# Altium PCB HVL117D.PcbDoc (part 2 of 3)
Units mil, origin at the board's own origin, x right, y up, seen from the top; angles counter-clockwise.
Board outline 2004.03 x 2004.03 mil, 6 copper layers (Top Layer, InternalPlane1, MidLayer1, InternalPlane2, MidLayer2, Bottom Layer), stack 60.56 mil thick; 218 components, 157 nets, 658 pads, 273 vias.
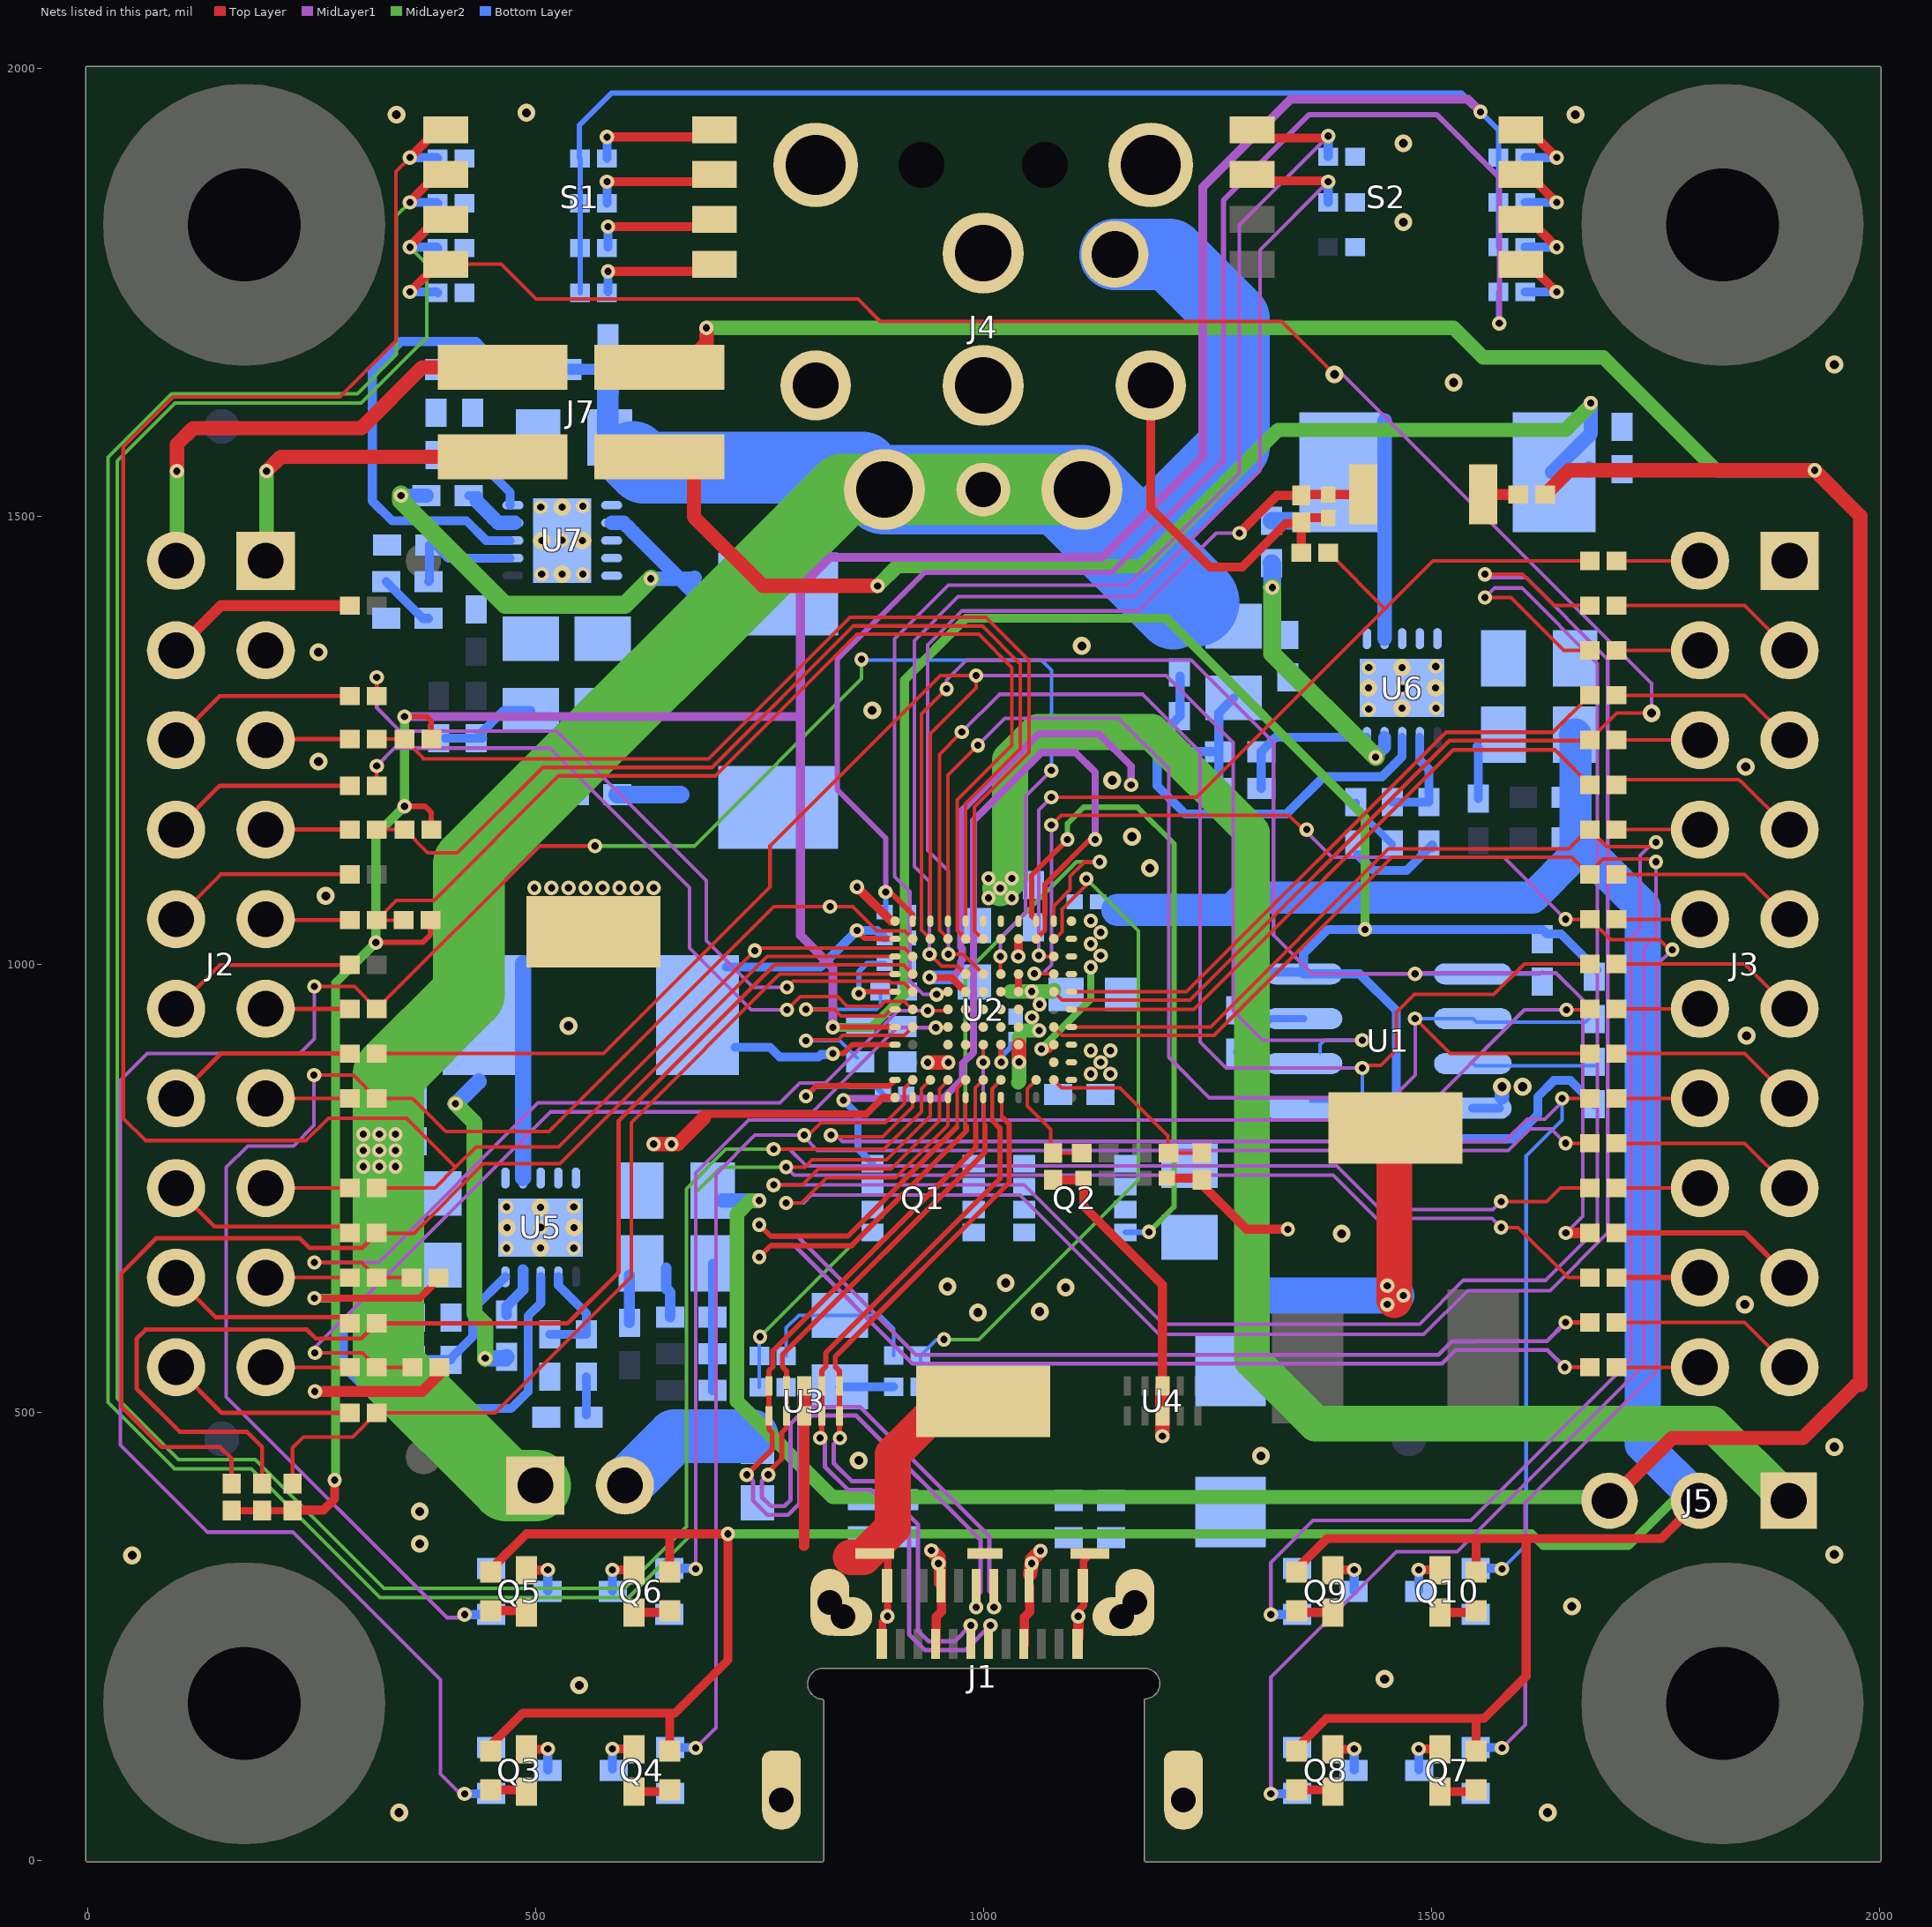
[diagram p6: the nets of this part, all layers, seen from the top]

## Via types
v1: diameter 16, hole 8, Top Layer to Bottom Layer, tented both sides, 166 vias
v2: diameter 16, hole 8.1, Top Layer to Bottom Layer, tented both sides, 54 vias
v3: diameter 20, hole 10, Top Layer to Bottom Layer, tented both sides, 41 vias
v4: diameter 19.68, hole 7.87, Top Layer to Bottom Layer, 12 vias

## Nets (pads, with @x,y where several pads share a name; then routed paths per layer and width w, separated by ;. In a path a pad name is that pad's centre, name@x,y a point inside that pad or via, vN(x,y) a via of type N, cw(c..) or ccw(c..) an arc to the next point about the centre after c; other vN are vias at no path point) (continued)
C_USB_B_N: J1.B7 U2.L7 U3.1 U3.10 | length 806.4
  Top Layer w4: 1020.68,828.32 U2.L7@1020.68,848.94
  Top Layer w5.8: v1(840,471) 839.37,471.63 U3.10@839.37,495.64 U3.1@839.37,529.1 839.37,546 834.8,550.57 834.8,561.8 1029,756 1029,821.27 1022.27,828
  MidLayer1 w4.8: v1(840,471) 833,464 833,443 853,423 878.86,423 927,374.86 927,256 939,244 968,244 v1(986,262)
C_USB_B_P: J1.B6 U2.K7 U3.2 U3.9 | length 875.1
  Top Layer w4: 1010,828 1010,860.94 U2.K7@1019.68,870.63
  Top Layer w5.8: v1(818,471) 819.69,472.69 U3.9@819.69,495.64 U3.2@819.69,529.1 819.69,546 824.25,550.57 824.25,566.17 1018.45,760.37 1018.45,816.9 1010,825.35 1010,828
  MidLayer1 w4.8: v1(818,471) 823.2,465.8 823.2,438.94 848.94,413.2 874.8,413.2 917.2,370.8 917.2,251.94 934.94,234.2 980.2,234.2 v1(1008,262)
C_USB_T_N: J1.A7 U2.L6 U3.4 U3.7 | length 1057.1
  Top Layer w4: 1001,820 U2.L6@1001,848.94
  Top Layer w5.8: v1@756,429 758.5,431.5 775,448 775,477 780.32,482.32 U3.7@780.32,495.64 U3.4@780.32,529.1 780.32,546 775.75,550.57 775.75,564 1002,790.25 1002,820
  MidLayer1 w4.8: v1(760,430) 752.9,422.9 752.9,405 762.9,395 778,395 785,402 785,486.86 803.94,505.8 862.2,505.8 1006.9,361.1 1006.9,300.1 1012,295 v1(1012,282) 1011,281 1011,278 1012.75,279.75 v1@1012.75,281.5
C_USB_T_P: J1.A6 U2.K6 U3.5 U3.6 | length 1076.2
  Top Layer w4: 991,822 991,861.63 U2.K6@1000,870.63
  Top Layer w5.8: v1(736,430) 764.45,458.45 764.45,477 760.63,480.82 U3.6@760.63,495.64 U3.5@760.63,529.1 760.63,546 765.2,550.57 765.2,568.37 991.45,794.62 991.45,822
  MidLayer1 w4.8: v1(736,430) 743.1,422.9 743.1,400.94 758.84,385.2 782.06,385.2 794.8,397.94 794.8,482.8 808,496 858.14,496 997.1,357.04 997.1,299.1 992,294 v1(992,282)
DEBUG_1: Q10.1 R61.1 U2.L2 | length 1570.6
  Top Layer w4: v1@829,813.37 835.37,807 887.63,807 921.26,840.63 U2.L2@921.26,850.94 ; v1@1650,850 R61.1@1677.04,850
  MidLayer1 w4: v1(830,809) 836,809 843,802 1582,802 1607,827 1627,827 v1@1650,850
  Bottom Layer w4: v1(1579,325) 1606,352 1606,786 1646,826 v1(1646,850)
  Bottom Layer w10: Q10.1@1549.5,325.59 v1@1578.41,325.59
DEBUG_2: Q4.1 R64.1 U2.K2 | length 1847.9
  Top Layer w4: v1@805,809 819,823 890.63,823 911.91,844.28 911.91,846.55 912,846.63 912,855.26 911.91,855.34 911.91,861.28 U2.K2@921.26,870.63 ; v1(1650,800) R64.1@1677.04,800
  MidLayer1 w4: v1(679,125) 701.5,147.5 701.5,765.5 745,809 v1(800,809) 800,807 815,792 1586.14,792 1610.14,816 1634,816 v1(1650,800)
  Bottom Layer w10: Q4.1@650.5,125.59 v1@678.41,125.59
DEBUG_3: R29.1 R65.1 S1.2 U2.L3 | length 4097
  Top Layer w4: v1(780,773.37) 801,773.37 809,781.37 892,781.37 940.94,830.32 U2.L3@940.94,850.94 ; v1(1578,706) 1597,706 1653,650 R65.1@1677.04,650
  Top Layer w10: v1(360,1850) 359,1850 S1.2@390,1881
  MidLayer1 w4: v1(780,773.37) 788.87,764.5 1390.5,764.5 1439,716 1568,716 v1(1578,706)
  MidLayer2 w4: v1(360,1850) 345,1835 345,1680 301.37,1636.37 93.7,1636.37 23,1565.67 23,511 97.37,436.63 183.01,436.63 326.64,293 604,293 679,368 679,745 707.37,773.37 v1(780,773.37)
  Bottom Layer w10: v1(360,1850) 390.04,1850 R29.1@391.04,1849
DEBUG_4: R25.1 R63.1 S1.3 U2.K3 | length 4045.7
  Top Layer w4: v1(766,793.37) 889,793.37 931,835.37 931,860.68 U2.K3@940.94,870.63 ; v1(1578,735) 1629,735 1644,750 R63.1@1677.04,750
  Top Layer w10: v1(360,1800) 359,1800 S1.3@388,1829
  MidLayer1 w4: v1(766,793.37) 783.63,793.37 802.5,774.5 1394.64,774.5 1443.14,726 1569,726 v1(1578,735)
  MidLayer2 w4: v1(360,1800) 379,1781 379,1699.33 305.67,1626 98,1626 33.37,1561.37 33.37,515.3 101.67,447 187.3,447 330.93,303.37 599.7,303.37 668.63,372.3 668.63,749.3 712.7,793.37 v1(766,793.37)
  Bottom Layer w10: v1(360,1800) 390.04,1800 R25.1@391.04,1799
DEBUG_CTL1: R55.1 S2.1 U2.E4 | length 1422
  Top Layer w4: v1@948,965 952.06,969.06 U2.E4@960.63,969.06
  Top Layer w10: S2.1@1306,1922 1383,1922 v1(1385,1924)
  MidLayer1 w4: v1@949,966 v1(948,966) 933,966 918,981 918,1080.75 901,1097.75 901,1363 961,1423 1161,1423 1286,1548 1286,1825 v1(1385,1924)
  Bottom Layer w10: v1(1385,1924) R55.1@1385.04,1901 R55.1@1385.04,1901
DEBUG_CTL2: R52.1 S2.2 U2.D5 | length 1334.2
  Top Layer w4: v1(940,1011) 953.5,997.5 971.56,997.5 U2.D5@980.32,988.74
  Top Layer w10: S2.2@1304,1874 1386,1874 v1(1385,1873)
  MidLayer1 w4: v1@940,1008 v1(940,1011) 940,1092 923,1109 923,1361 972,1410 1168,1410 1309,1551 1309,1797 v1(1385,1873)
  Bottom Layer w10: v1(1385,1873) R52.1@1385.04,1850 R52.1@1385.04,1850
"EXTERNAL POWER": C22.1 C23.1 C33.1 C34.1 C44.1 C45.1 J4.1 J4.2 J4.3 J6.1 pad.0 R81.2 R91.2 R101.2 U5.1 U6.1 U7.1 | length 3136.3
  MidLayer2 w80: J6.1@500,418 468,418 336,550 336,877 425.9,966.9 425.9,1111.9 843.53,1529.53 J4.3@889.76,1529.53 J4.1@1000,1529.53 J4.2@1110.24,1529.53
  Bottom Layer w12: R101.2@535.74,1663.69 568.69,1663.69 C45.1@581,1651.38
  Bottom Layer w24: C44.1@581,1589.8 C45.1@581,1651.38
  Bottom Layer w80: 609,1566 621,1554 865.29,1554 J4.3@889.76,1529.53 ; J4.2@1073.47,1529.53 1212,1391 ; pad.0@1147,1792 1208,1792 1280,1720 1280,1577 1171.38,1468.38
  Bottom Layer w100: J4.3@889.76,1529.53 J4.1@1000,1529.53 1073.47,1529.53 J4.2@1110.24,1529.53 1171.38,1468.38 1235.76,1404
  other v1: 308,774 326,774 344,774 308,792 326,792 344,792 308,810 326,810 344,810
GND: C1.2 C2.2 C3.2 C4.2 C5.2 C6.2 C7.2 C8.2 C9.2 C10.2 C11.2 C12.2 C13.2 C14.2 C15.2 C16.2 C17.2 C18.2 C19.2 C22.2 C23.2 C24.2 C25.2 C26.2 C28.2 C29.2 C30.2 C33.2 C34.2 C35.2 C36.2 C37.2 C39.2 C40.2 C41.2 C44.2 C45.2 C46.2 C47.2 C48.2 C50.2 C51.2 C52.2 C53.2 D1.2 J1.1 J1.2 J1.3 J1.A1 J1.A12 J1.B1 J1.B12 J1.H1 J1.H2 J1.H3 J1.H4 J1.H5 J1.H6 J1.H7 J1.H8 J2.3 J3.1 J4.4 J4.5 J4.6 J4.7 J4.8 J4.9 Q3.2 Q4.2 Q5.2 Q6.2 Q7.2 Q8.2 Q9.2 Q10.2 R21.2 R22.2 R24.2 R25.2 R26.1 R28.1 R29.2 R30.2 R33.2 R49.2 R52.2 R55.2 R56.1 R70.1 R83.1 R84.1 R88.1 R93.1 R94.1 R97.1 R103.1 R104.1 R109.1 TP4.1 TP5.1 U1.4 U2.A1 U2.B8 U2.D8 U2.E5 U2.E6 U2.E7 U2.E8 U2.F5 U2.F6 U2.F7 U2.F8 U2.G5 U2.G6 U2.G7 U2.G8 U2.H4 U2.H5 U2.H8 U2.L1 U3.3 U3.8 U4.3 U4.8 U5.3 U5.4 U5.5 U5.11 U6.3 U6.4 U6.5 U6.11 U7.3 U7.4 U7.5 U7.11 | length 3329
  Top Layer w6: R22.2@1077.02,760.47 R22.2@1077.02,761 ; C15.2@1110.06,759.04 C15.2@1112.02,761 ; R30.2@1237.04,761 R30.2@1239,759.04
  Top Layer w8: 687.5,832.5 869.5,832.5 887.94,850.94 U2.L1@901.57,850.94 ; J1.B12@887.48,240.35 887.48,266.48 v1(893,272) 893,304.93 893.39,305.31 893.39,334.39 894,335 ; v2(940,985) 964.37,985 U2.E5@980.32,969.06 ; U2.E8@1039.37,969.06 U2.D8@1039.37,988.74 ; J1.B1@1105.98,240.35 v1(1106,272) 1106,278 1112,284 1112,305.2 1111.89,305.31 1111.89,333.46 J1.1@1119.76,341.34
  Top Layer w10: 799,350 800,351 ; v1(859,1086) 897.2,1047.8 U2.A1@901.57,1047.8 ; v2(1039,1008.37) 1039.37,1008.74 U2.B8@1039.37,1028.11 ; R22.2@1078,759.04 C15.2@1110.06,759.04 ; C15.2@1112.02,761 1112.02,729.98 1200,642 U4.8@1200,495.64 ; J4.6@1187.01,1645.67 1187.01,1508.99 1253,1443 1289,1443 1337.68,1491.68 1353.64,1491.68 R26.1@1355,1493.04 1359.97,1498.01 C53.2@1385,1498.01 ; C19.2@1204.99,761 R30.2@1237.04,761 ; R30.2@1239,759.04 1294.04,704 v1(1340,704) ; R70.1@1355.04,1459 R26.1@1355,1493.04
  Top Layer w12: v1(254,523) 374,523 392.96,541.96 R24.2@392.96,550 ; 800,351 U3.8@800,495.64 ; v1(1106,272) 1106.3,271.7 J1.B1@1106.3,248.3
  Top Layer w15: U3.8@800,495.64 U3.3@800,529.1
  Top Layer w16: v1(632,799) v1(652,799) 659,799 688.5,828.5 ; v2(938,890) v2(961,890) ; v2(1040,890.67) U2.H8@1040,909.37 ; v1(1200,473) U4.8@1200,495.64 U4.3@1200,529.1
  Top Layer w40: 852,338 866,338 899,371 899,453 958,512 TP4.1@1000,512
  MidLayer1 w8: v2(940,985) 965,985 975,995 975,1003.08 976.5,1004.58 976.5,1017.42 975,1018.92 975,1170 1062,1257 1129,1257 1165,1221 v2(1165,1200)
  MidLayer2 w16: 1030,969 1030.37,969.37 v2(1054,969.37) 1077.37,969.37 1079,971 ; 1039,868 1040,869 v2(1040,890.67) 1040,918 ; 1042.33,925.67 v2(1062.3,925.67)
  Bottom Layer w8: C40.2@1416,1180.62 1416,1173.98 C39.2@1456.6,1133.38
  Bottom Layer w10: R93.1@1219.6,1229.38 1227.22,1237 C41.2@1262.98,1237 ; R97.1@1262.98,1196 C41.2@1262.98,1237 ; C33.2@1279.6,1297 1262.98,1280.38 C41.2@1262.98,1237 ; U1.4@1546.49,839 U1.4@1576,839 ; 1551,1243 1552.6,1241.4 R94.1@1552.6,1184.62
  Bottom Layer w12: R84.1@605,599.62 C25.2@605,653 ; 646.1,660.8 646.1,637.96 650.38,633.68 C26.2@650.38,606
  Bottom Layer w15: v2(940,985) 964.37,985
  Bottom Layer w16: 1579,851 v3(1579,863)
  other v2: 468,683 543,683 506,706 468,729 543,729 1054.3,940.57 1062.8,955.07 499,1085 518,1085 537,1085 556,1085 575,1085 594,1085 613,1085 632,1085 1430.2,1284.4 1505.3,1285.5 1467.6,1307.67 1430.2,1330.7 1505,1332.1 507,1435 553,1435 530,1473 506,1510 553,1511
  other v3: 348,53 1630,53 549,195 1448,202 1657,283 50,340 1950,341 371,353 371,389 861,446 1310,451 1950,461 994,611 1063,612 1850,620 1092,639 960,640 1025,644 1400,699 1602,863 1852,920 537,931 266,1076 1186,1107 1166,1142 1144,1205 1851,1220 258,1226 876,1283 258,1348 1110,1355 1525,1649 1950,1669 1469,1828 1469,1916 345,1948 1661,1948 490,1950
  other v4: 506,683.36 468.6,706 543.4,706 506,728.64 1467.6,1285.36 1430.2,1308 1505,1308 1467.6,1330.64 530.12,1435.28 507.48,1472.69 552.76,1472.69 530.12,1510.09
GPIO0: Q5.1 R35.1 U2.B2 | length 1636.4
  Top Layer w4: v1(253,876) 296.96,876 R35.1@322.96,850 363,850 400,813 515,813 766,1064 v1(829,1064) 854.47,1064 881.47,1037 912.37,1037 U2.B2@921.26,1028.11
  MidLayer1 w4: v1(253,876) 253,820 230,797 179,797 155,773 155,517 401.5,270.5 v1@417.5,270.5
  Bottom Layer w10: v1(421,274) Q5.1@450.09,274
GPIO1: R33.1 R37.1 S1.1 U2.C2 | length 2526.5
  Top Layer w4: R37.1@322.96,750 388,750 411,773 ; v1(360,1900) 344.5,1884.5 344.5,1695.5 282,1633 96,1633 40,1577 40,828 65,803 244,803 269,828 356,828 411,773 ; U2.C2@921.26,1008.43 911.68,1018 748,1018 v1(745,1015) 526,796 434,796 411,773
  Top Layer w10: v1(360,1900) S1.1@398,1938
  Bottom Layer w10: v1(360,1900) 390.04,1900 R33.1@391.04,1899
GPIO2: Q7.1 R57.1 U2.D10 | length 1964.3
  Top Layer w4: v1(1057,989.37) 1078.11,989.37 U2.D10@1078.74,988.74 ; v1@1082,1155 v1(1076,1155) 1087,1166 1341,1166 v1@1357,1150 ; v1(1650,1050) R57.1@1677.04,1050 1700.04,1027 1755,1027 1766,1016 v1(1769,1016)
  MidLayer1 w4: v1(1057,989.37) 1066.46,989.37 1076,998.91 v1(1076,1155) ; v1@1358,1150 1389,1119 1581,1119 v1(1650,1050) ; v1(1579,125) 1605,151 1605,398.99 1752,545.99 1752,999 v1(1769,1016)
  Bottom Layer w10: Q7.1@1549.5,125.59 v1@1578.41,125.59
  other v1: 1361,1150
GPIO3: Q9.1 R53.1 U2.G11 | length 1923
  Top Layer w4: U2.G11@1098.43,929.69 1253.69,929.69 1452.35,1128.35 1653.35,1128.35 R53.1@1673,1148 ; R53.1@1677.04,1150 1696.04,1131 1746,1131 v1(1751,1136)
  MidLayer1 w4: v1(1321,274) 1321,332 1368,379 1544,379 1723,558 1723,1029 1733,1039 1733,1121 1748,1136 v1(1751,1136)
  Bottom Layer w10: v1(1321,274) Q9.1@1350.09,274
GPIO4_HPD: R46.2 R70.2 U2.C10 | length 1002.2
  Top Layer w4: v1(1062,1009.37) 1062.94,1008.43 U2.C10@1078.74,1008.43 ; v1(1076,1186) 1238,1186 1448.46,1396.46 ; R70.2@1384.96,1459 1385.91,1459 1448.46,1396.46 ; R46.2@1677.04,1450 1502,1450 1448.46,1396.46
  MidLayer1 w4: v1(1062,1009.37) 1062,1172 v1(1076,1186) v1@1078,1188
GPIO5_HPD: R21.1 R50.2 S1.4 U2.E10 | length 2455
  Top Layer w4: S1.4@400,1781 462,1781 501,1742 860,1742 885,1717 1333,1717 v3(1392,1658) ; U2.E10@1078.74,969.06 1088.09,959.71 1230.71,959.71 1520.34,1249.34 R50.2@1676.38,1249.34 ; R50.2@1674.69,1247.65 R50.2@1676.38,1249.34 ; R50.2@1677.04,1249.34 R50.2@1676.38,1249.34 ; v3(1746,1280) 1707.04,1280 R50.2@1677.04,1250 R50.2@1676.38,1249.34
  Top Layer w10: v1(360,1750) S1.4@391,1781
  MidLayer1 w4: v3(1392,1658) 1401,1658 1746,1313 v3(1746,1280)
  Bottom Layer w10: v1(360,1750) 390.04,1750 R21.1@391.04,1749
GPIO6: Q8.1 R58.1 U2.G10 | length 2056.2
  Top Layer w4: U2.G10@1078.74,929.69 1088.09,920.34 1257.56,920.34 1456.22,1119 1657,1119 R58.1@1673,1103 ; R58.1@1677.04,1100 1677.04,1102.04 1692,1117 v1@1751,1117
  MidLayer1 w4: v1(1321,74) 1321,204 1461,344 1528.8,344 1737,552.2 1737,1017 1751,1031 v1(1751,1114)
  Bottom Layer w10: v1(1321,74) Q8.1@1350.09,74
GPIO7: Q3.1 R36.1 U2.D7 | length 2713.1
  Top Layer w4: v1(253.33,975) 297.96,975 R36.1@322.96,950 504.66,1131.7 v1(566.6,1131.7) ; v1(1019,1008.37) 1019,989.43 U2.D7@1019.68,988.74
  MidLayer1 w4: v1(253.33,975) 253.33,916.33 237,900 67,900 37,870 37,463 134,366 229.26,366 394,201.26 394,96 v1@418.5,71.5 ; v1(1019,1008.37) 1019,1029 1047,1057 1047,1187 v1(1076,1216) v1@1077.5,1217.5
  MidLayer2 w4: v1(566.6,1131.7) 677.4,1131.7 864,1318.3 v1(864,1340)
  Bottom Layer w4: v1(864,1340) 869,1340 870,1339 1065,1339 1076,1328 v1(1076,1216)
  Bottom Layer w10: v1(421,74) Q3.1@450.09,74
GPIO8: Q6.1 R59.1 U2.H6 | length 1628.8
  Top Layer w4: v1(1000,890.37) U2.H6@1000,910 ; v1(1651,949) 1676.04,949 R59.1@1677.04,950
  MidLayer1 w4: v1(679,325) 679,767 738,826 1000,826 ; v1(1000,890.37) 1000,826 ; v1(1651,949) 1604,949 1481,826 1000,826
  Bottom Layer w10: Q6.1@649.5,325.59 v1@678.41,325.59
HV_GATE1: Q1.4 U2.B9 | length 916.9
  Top Layer w5: U2.B9@1059.06,1028.11 1068.94,1038 1068.94,1054.94
  Top Layer w6: 1068.94,1054.94 1068.94,1088.94 1120,1140 v1@1125,1140
  Top Layer w8: U2.B9@1059.06,1028.11 U2.B9@1059.06,1028.11
  MidLayer1 w8: v2(844,848) 844,850 955,850 977,872 977,889.29 989,901.29 989,1160 1065,1236 1103,1236 1125,1214 v1(1125,1139)
  Bottom Layer w8: v2@844,850 v2(844,848) 860,832 860,793.72 Q1.4@876.34,777.39
HV_GATE2: Q2.4 U2.A9 | length 742.4
  Top Layer w6: U2.A9@1059.06,1047.8 1059.06,1048.94 1054,1054 1054,1099 v1(1094,1139)
  MidLayer2 w6: v1(1094,1139) 1094,1157 1112,1175 1172,1175 1213,1134 1213,729 v2(1185,701)
  Bottom Layer w6: Q2.4@1158.66,700.61 1184.61,700.61 v2(1185,701)
HV_SOURCE: C4.1 C5.1 C46.1 C47.1 C48.1 C49.1 J5.1 L4.2 R102.2 U2.A6 U2.A7 U2.A8 U2.B7 | length 1916.3
  MidLayer2 w40: v2(1018.81,1084.59) 1030,1095.78 1030,1228 1061,1259 1188,1259 1300,1147 1300,558 1371,487 1813,487 J5.1@1899,401
  Bottom Layer w10: C49.1@399.12,1252.06 R102.2@441.12,1252.06 ; R102.2@434.12,1252.28 464.83,1283 C47.1@495,1283
  Bottom Layer w20: C48.1@591.62,1189 662,1189
  other v2: 1005.81,1073.59 1031.81,1073.59 1005.81,1095.59 1031.81,1095.59
I2C_IRQ1Z: R40.2 R78.1 U2.C1 | length 1343.7
  Top Layer w4: R40.2@322.96,699.46 364.46,699.46 442,777 527.46,777 758.89,1008.43 U2.C1@901.57,1008.43
  Top Layer w4.8: R78.1@161,419.92 161,448 148,461 83,461 38,506 38,655 77,694 237,694 248,683 306.5,683 322.96,699.46 R40.2@322.96,700
I2C_IRQ2Z: R16.1 R77.1 U2.B6 | length 1162.9
  Top Layer w4: R16.1@322.96,1251 R77.1@354.04,1251 375.04,1230 ; 375.04,1229 693.13,1229 851.13,1387 1002.87,1387 1051,1338.87 1051,1236.13 990,1175.13 990,1037 998.89,1028.11 U2.B6@1000,1028.11
I2C_SCL1: R69.2 R79.1 U2.D2 | length 1414.5
  Top Layer w4: 767,999 911,999 U2.D2@921.26,988.74
  Top Layer w4.8: R79.1@195,419.92 195,461 178,478 103,478 55,526 55,582 65,592 245,592 255,582 305.96,582 R69.2@322.96,599 536,599 593,656 593,825 767,999
I2C_SCL2: R32.1 R75.1 U2.B5 | length 1211.6
  Top Layer w4: R75.1@346,1049 R32.1@322.96,1049 344.96,1071 387,1071 526,1210 701,1210 859,1368 995,1368 1032,1331 1032,1244 971,1183 971,1037.43 U2.B5@980.32,1028.11
I2C_SDA1: R71.2 R80.1 U2.D1 | length 1032.4
  Top Layer w4: R80.1@229,419.92 229,460 241,472 295.96,472 R71.2@322.96,499 455,499 607,651 607,823 772.74,988.74 U2.D1@901.57,988.74
I2C_SDA2: R17.1 R76.1 U2.A5 | length 1164
  Top Layer w4: R17.1@322.96,1150 R76.1@354.04,1150 380.04,1124 413,1124 508.32,1219.32 697.14,1219.32 855.14,1377.32 998.86,1377.32 1041.32,1334.86 1041.32,1240.14 980.32,1179.14 U2.A5@980.32,1047.8
LDO_1V8D: C16.1 R45.2 U2.A2 | length 1732.9
  Top Layer w6: v1(891,1080.37) 896,1080.37 921.26,1055.11 U2.A2@921.26,1047.8 U2.A2@921,1048.06
  MidLayer1 w6: v1(891,1080.37) 891,1140.78 837,1194.78 837,1340 934,1437 1143,1437 1268,1562 1268,1852 1364,1948 1506,1948 1576,1878 v1@1576,1719
  Bottom Layer w6: C16.1@891,1058 v1(891,1080.37) ; R45.2@1575.04,1750 1575.04,1719.96 v1@1576,1719
  other v1: 1576,1715
LDO_3V3: C2.1 C14.1 R4.1 R7.1 R8.1 R9.2 R12.2 R13.2 R14.2 R15.2 R20.2 R42.2 R43.2 R44.2 R75.2 R76.2 R77.2 R78.2 R79.2 R80.2 U1.8 U2.G1 | length 7191.5
  Top Layer w6: v1(322,1024) 374,1024 382.96,1032.96 R75.2@382.96,1049 ; v1(354,1176) 377,1176 383.96,1169.04 R76.2@383.96,1150 ; v1(354,1276) 379,1276 383.96,1271.04 R77.2@383.96,1251 ; v1@831.37,930 v1(832,929.37) ; v1@832.32,929.69 U2.G1@901.57,929.69
  Top Layer w8: R78.2@161,390 R79.2@195,390 R80.2@229,390 ; v1(253.33,627) 371,627 391.96,647.96 R20.2@391.96,650
  Top Layer w10: R80.2@229,390 R80.2@229,390 229.6,390.6 263.6,390.6 276,403 v1(276,424) ; v1(832,929.37) v1@832.32,929.69
  MidLayer1 w10: v1(354,1276) 796,1276 ; v1(832,929.37) 832,996 796,1032 796,1276 ; v1(1555,1951) 1541,1965 1343,1965 1245,1867 1245,1566 1132.75,1453.75 828.75,1453.75 796,1421 796,1276
  MidLayer2 w10: v1(253.33,627) 277,627 ; v1@277,424 277,627 ; v1(354,1276) v1(354,1176) 322,1144 v1(322,1024) 277,979 277,627 ; v1(832,929.37) 875.37,929.37 912,966 912,1317 981,1386 1204,1386 1426,1164 v1(1426,1038.62)
  Bottom Layer w6: R15.2@550.04,1749 R14.2@550.04,1799 R13.2@550.04,1849 R12.2@550.04,1899 549,1900.04 549,1936 585,1972 1534,1972 v1(1555,1951) 1576,1930 ; v1(832,929.37) 861.38,929.37 C14.1@862.38,930.37 ; R44.2@1575.04,1800 R43.2@1575.04,1850 R42.2@1575.04,1900 1575.04,1929.04
  Bottom Layer w8: R8.1@1283,948.62 1287,952.62 C2.1@1287,991.01
  Bottom Layer w10: C2.1@1287,991.01 U1.8@1355.51,991 ; R9.2@1682,843.38 1655.38,870 1637,870 1619,852 1619,832 1592,805 1489,805 1461,833 1461,948 1420,989 U1.8@1357.51,989 1357.51,1011.51 1384.62,1038.62 v1(1426,1038.62) 1624,1038.62 1629.12,1033.5 1645,1033.5 R7.1@1685,993.5
LSX_P2R: R48.2 U2.L4 | length 2225.6
  Top Layer w4: v1(780,733.37) 797,733.37 825,761.37 902,761.37 960.63,820 U2.L4@960.63,850.94 ; v1(1560,1435) 1602,1435 1637,1400 R48.2@1677.04,1400
  MidLayer1 w4: v1(780,733.37) 799.37,733.37 808,742 1040.92,742 1196.29,586.63 1491.71,586.63 1540.71,635.63 1632.63,635.63 1697,700 1697,1340.08 1606.08,1431 v1@1560,1431
LSX_R2P: R47.2 U2.K4 | length 2228.7
  Top Layer w4: v1(766,753.37) 798,753.37 816,771.37 897,771.37 951,825.37 951,860.37 U2.K4@960.63,870 ; v1(1560,1409) 1589,1409 1648,1350 R47.2@1677.04,1350
  MidLayer1 w4: v1(766,753.37) 1045.63,753.37 1201,598 1487,598 1536,647 1627.92,647 1685.63,704.71 1685.63,1335.37 1601.37,1419.63 1570.63,1419.63 v1(1560,1409)
MRESET: R51.1 U2.E11 | length 715.7
  Top Layer w4: U2.E11@1098.43,969.06 1226.84,969.06 1516.47,1258.68 1635.72,1258.68 R51.1@1677.04,1300
NetC1_1: C1.1 J6.2 R1.1 R2.2 R5.2 | length 224.3
  Bottom Layer w10: R1.1@840,528 R5.2@900.04,528
  Bottom Layer w60: J6.2@600,418 655,473 C1.1@741.5,473
NetC3_1: C3.1 U2.H7 | length 42.4
  Top Layer w6: U2.H7@1019.68,910 1019.68,890.69 v1(1020,890.37)
  Bottom Layer w6: v1@1016.7,893.67 1031,907.97 C3.1@1031,910.38
NetC6_1: C6.1 L1.1 Q2.1 Q2.2 Q2.3 U2.H11 U2.J10 U2.J11 U2.K11
  other v2: 1120,877.37 1142,877.37 1131,890.37 1120,903.37 1142,903.37
NetC17_1: C17.1 U2.K1 | length 202.1
  Top Layer w6: v1(802,852.37) 813.63,864 837.49,864 837.99,864.5 850.01,864.5 850.51,864 894.94,864 U2.K1@901.57,870.63
  Bottom Layer w6: v1(802,852.37) 813.63,864 879.01,864 C17.1@888.01,855
NetC18_1: C18.1 U2.E1 | length 100.2
  Top Layer w6: v1(861,967) 861,969.37 861.32,969.06 U2.E1@901.57,969.06
  Bottom Layer w6: v1(861,967) 861,991.37 870,1000.37 C18.1@890.01,1000.37
NetC20_1: C20.1 U5.9 | length 58.1
  Bottom Layer w12: C20.1@468,608.62 468,618 486.31,636.31 U5.9@486.31,650.88 486.31,658.69 U5.9@486,659
NetC20_2: C20.2 L2.1 U5.2 | length 598.3
  MidLayer2 w18: v1(411,844) 432,823 432,610 444,598 v1(444,560)
  Bottom Layer w18: v1(411,844) 412,844 437,869 ; v1(444,560) 466.62,560 C20.2@468,561.38 ; U5.2@486.31,761.12 L2.1@486.31,1000.81
NetC28_1: C28.1 R85.2 U5.7 | length 118.2
  Bottom Layer w10: C28.1@516,586.62 R85.2@557,586.62 557,610 525.68,641.32 U5.7@525.68,650.88
NetC29_1: C29.1 R85.1 | length 42.8
  Bottom Layer w10: C29.1@557,496.62 R85.1@557,539.38
NetC30_1: C30.1 R88.2 U5.10 | length 158.8
  Bottom Layer w10: R88.2@365,558.38 C30.1@406,558.38 ; C30.1@406,558.76 405.38,559.38 430,584 430,614.25 U5.10@466.63,650.88
NetC31_1: C31.1 U6.9 | length 289.6
  MidLayer2 w20: v1(1322.6,1420.1) 1322.6,1346.4 v1(1438,1231)
  Bottom Layer w10: v1@1440,1231 v1@1440,1234
  Bottom Layer w14: v1@1440,1234 1447.91,1241.91 U6.9@1447.91,1252.88
  Bottom Layer w20: C31.1@1322,1447.38 1322.6,1446.78 v1(1322.6,1420.1)
NetC31_2: C31.2 L3.1 U6.2 | length 274.3
  Bottom Layer w16: U6.2@1447.91,1363.12 1447.91,1606.71
  Bottom Layer w20: C31.2@1322,1494.62 L3.1@1352.68,1494.62
NetC39_1: C39.1 R95.2 U6.7 | length 117.5
  Bottom Layer w10: C39.1@1456.6,1180.62 R95.2@1497.6,1180.62 1497.6,1217 1487.28,1227.32 U6.7@1487.28,1252.88
NetC40_1: C40.1 R95.1 | length 105.6
  Bottom Layer w10: C40.1@1418,1122 1435.64,1104.36 1472.6,1104.36 1501.22,1132.98 R95.1@1501.22,1129.76
NetC41_1: C41.1 R97.2 U6.10 | length 165.6
  Bottom Layer w10: R97.2@1310.22,1196 C41.1@1310.22,1237 1326.1,1252.88 U6.10@1428.23,1252.88
NetC42_1: C42.1 U7.9 | length 63
  Bottom Layer w10: C42.1@425.74,1522.69 C42.1@436.12,1522.69
  Bottom Layer w16: C42.1@434.55,1516.6 451.69,1499.11 458.43,1492.37 U7.9@475,1492.37 U7.9@477,1492.37
NetC42_2: C42.2 L4.1 U7.2 | length 606.4
  MidLayer2 w20: v1@350,1524 350,1517 466,1401 600,1401 v1(629,1430)
  Bottom Layer w16: v1(350.12,1522.69) C42.2@378.5,1522.69 ; U7.2@585.24,1492.37 598.63,1492.37 602.5,1488.5 602.76,1488.5 609.5,1481.76 609.5,1481.5 661,1430 ; v1(629,1430) 661,1430 ; 678,1431 677,1430 661,1430 ; L4.1@718.13,1411.13 699,1392 661,1430
NetC50_1: C50.1 R108.2 U7.7 | length 127.1
  Bottom Layer w10: R108.2@380.74,1426.69 381.74,1427.68 C50.1@381.74,1467.69 ; C50.1@391.12,1464.69 402.8,1453 U7.7@472,1453
NetC51_1: C51.1 R108.1 | length 64.2
  Bottom Layer w10: R108.1@333.5,1426.69 374.5,1385.69 C51.1@380.74,1385.69
NetC52_1: C52.1 R109.2 U7.10 | length 114.4
  Bottom Layer w10: C52.1@389.12,1568.06 R109.2@430.12,1568.06 472,1526.18 U7.10@472,1512.06
NetD2_2: D2.2 R72.2 | length 38
  Top Layer w10: D2.2@450,78.35 R72.2@488.03,78.35
NetD3_2: D3.2 R73.2 | length 38
  Top Layer w10: R73.2@610,76.38 D3.2@648.03,76.38
NetD4_2: D4.2 R74.2 | length 38
  Top Layer w10: D4.2@450,278.35 R74.2@488.03,278.35
NetD5_2: D5.2 R86.2 | length 38
  Top Layer w10: R86.2@610,276.38 D5.2@648.03,276.38
NetD6_2: D6.2 R87.2 | length 38
  Top Layer w10: R87.2@1510,76.38 D6.2@1548.03,76.38
NetD7_2: D7.2 R89.2 | length 38
  Top Layer w10: D7.2@1350,78.35 R89.2@1388.03,78.35
NetD8_2: D8.2 R90.2 | length 38
  Top Layer w10: D8.2@1351.97,276.38 R90.2@1390,276.38
NetD9_2: D9.2 R96.2 | length 38
  Top Layer w10: R96.2@1510,276.38 D9.2@1548.03,276.38
NetJ2_4: J2.4 R18.2 | length 214.8
  Top Layer w12: J2.4@99,1350 149,1400 R18.2@293.04,1400
NetJ2_5: J2.5 R16.2 | length 93
  Top Layer w4.8: J2.5@200,1251 R16.2@293.04,1251
NetJ2_6: J2.6 R19.2 | length 214.3
  Top Layer w4.8: J2.6@99,1250 148,1299 R19.2@293.04,1299
NetJ2_7: J2.7 R17.2 | length 94
  Top Layer w4.8: J2.7@199,1150 R17.2@293.04,1150
NetJ2_8: J2.8 R23.1 | length 214.3
  Top Layer w4.8: J2.8@99,1150 148,1199 R23.1@293.04,1199
NetJ2_9: J2.9 R32.2 | length 94.5
  Top Layer w4.8: J2.9@199,1050 200,1049 R32.2@293.04,1049
NetJ2_10: J2.10 R31.1 | length 214.8
  Top Layer w4.4: J2.10@99,1050 149,1100 R31.1@293.04,1100
NetJ2_11: J2.11 R36.2 | length 94
  Top Layer w4.8: J2.11@199,950 R36.2@293.04,950
NetJ2_12: J2.12 R34.1 | length 214.3
  Top Layer w4.4: J2.12@99,950 148,999 R34.1@293.04,999
NetJ2_13: J2.13 R35.2 | length 93
  Top Layer w4: J2.13@200,850 R35.2@293.04,850
NetJ2_14: J2.14 R38.1 | length 214.8
  Top Layer w4.8: J2.14@99,850 149,900 R38.1@293.04,900
NetJ2_15: J2.15 R37.2 | length 93
  Top Layer w4: J2.15@200,750 R37.2@293.04,750
NetJ2_16: J2.16 R40.1 | length 204.9
  Top Layer w4.8: J2.16@99,750 142,707 R40.1@286.04,707
NetJ2_17: J2.17 R39.2 | length 93
  Top Layer w4: J2.17@200,650 R39.2@293.04,650
NetJ2_18: J2.18 R69.1 | length 206
  Top Layer w4.8: J2.18@99,650 143.5,605.5 ; 144,606 R69.1@287.04,606
NetJ2_19: J2.19 R41.2 | length 93
  Top Layer w4: J2.19@200,550 R41.2@293.04,550
NetJ2_20: J2.20 R71.1 | length 215.2
  Top Layer w4.8: J2.20@99,550 150,499 R71.1@293.04,499
NetJ3_2: J3.2 R46.1 | length 93
  Top Layer w4: R46.1@1706.96,1450 J3.2@1800,1450
NetJ3_3: J3.3 R48.1 | length 213.8
  Top Layer w4: R48.1@1706.96,1400 1850,1400 J3.3@1900,1350
NetJ3_4: J3.4 R47.1 | length 93
  Top Layer w4: R47.1@1706.96,1350 J3.4@1800,1350
NetJ3_5: J3.5 R51.2 | length 213.8
  Top Layer w4: R51.2@1706.96,1300 1850,1300 J3.5@1900,1250
NetJ3_6: J3.6 R50.1 | length 93
  Top Layer w4: R50.1@1706.96,1250 J3.6@1800,1250
NetJ3_7: J3.7 R54.2 | length 218.7
  Top Layer w4: R54.2@1706.96,1200 1712.96,1206 1843.08,1206 1844.58,1204.5 1845.5,1204.5 J3.7@1900,1150
NetJ3_8: J3.8 R53.2 | length 93
  Top Layer w4: R53.2@1706.96,1150 J3.8@1800,1150
NetJ3_9: J3.9 R58.2 | length 213.8
  Top Layer w4: R58.2@1706.96,1100 1850,1100 J3.9@1900,1050
NetJ3_10: J3.10 R57.2 | length 93
  Top Layer w4: R57.2@1706.96,1050 J3.10@1800,1050
NetJ3_11: J3.11 R60.2 | length 213.8
  Top Layer w4: R60.2@1706.96,1000 1850,1000 J3.11@1900,950
NetJ3_12: J3.12 R59.2 | length 93
  Top Layer w4: R59.2@1706.96,950 J3.12@1800,950
NetJ3_13: J3.13 R62.2 | length 213.8
  Top Layer w4: R62.2@1706.96,900 1850,900 J3.13@1900,850
NetJ3_14: J3.14 R61.2 | length 93
  Top Layer w4: R61.2@1706.96,850 J3.14@1800,850
NetJ3_15: J3.15 R64.2 | length 213.8
  Top Layer w4: R64.2@1706.96,800 1850,800 J3.15@1900,750
NetJ3_16: J3.16 R63.2 | length 93
  Top Layer w4: R63.2@1706.96,750 J3.16@1800,750
NetJ3_17: J3.17 R66.1 | length 213.8
  Top Layer w5.8: R66.1@1706.96,700 1850,700 J3.17@1900,650
NetJ3_18: J3.18 R65.2 | length 93
  Top Layer w5.8: R65.2@1706.96,650 J3.18@1800,650
NetJ3_19: J3.19 R68.1 | length 213.8
  Top Layer w4: R68.1@1706.96,600 1850,600 J3.19@1900,550
NetJ3_20: J3.20 R67.1 | length 93
  Top Layer w4: R67.1@1706.96,550 J3.20@1800,550
NetQ1_1: Q1.1 Q1.2 Q1.3 R1.2 R3.2 R6.2 | length 193.5
  Bottom Layer w4: R3.2@779.96,562.5 779.96,593.96 794,608 R1.2@840,608 885,608 900.04,592.96 R6.2@900.04,563
NetQ1_5: Q1.5 Q1.6 Q1.7 Q1.8 Q2.5 Q2.6 Q2.7 Q2.8
NetQ3_3: Q3.3 R72.1 | length 47.1
  Top Layer w10: R72.1@490,123.62 v1@513.62,123.62
  Bottom Layer w10: Q3.3@514,100.5 v1(514,124)
NetQ4_3: Q4.3 R73.1 | length 46.1
  Top Layer w10: v1(586,124) R73.1@609.62,124
  Bottom Layer w10: Q4.3@586,101.5 v1(586,124)
NetQ5_3: Q5.3 R74.1 | length 47.1
  Top Layer w10: R74.1@490,323.62 v1@513.62,323.62
  Bottom Layer w10: Q5.3@514,300.5 v1(514,324)
NetQ6_3: Q6.3 R86.1 | length 47.1
  Top Layer w10: v1(586,324) R86.1@609.62,324
  Bottom Layer w10: Q6.3@586,300.5 v1(586,324)
NetQ7_3: Q7.3 R87.1 | length 47.1
  Top Layer w10: v1(1486,124) R87.1@1509.62,124
  Bottom Layer w10: Q7.3@1486,100.5 v1(1486,124)
NetQ8_3: Q8.3 R89.1 | length 47.1
  Top Layer w10: R89.1@1390,123.62 v1@1413.62,123.62
  Bottom Layer w10: Q8.3@1414,100.5 v1(1414,124)
NetQ9_3: Q9.3 R90.1 | length 47.1
  Top Layer w10: R90.1@1390.38,324 v1(1414,324)
  Bottom Layer w10: Q9.3@1414,300.5 v1(1414,324)
NetQ10_3: Q10.3 R96.1 | length 47.1
  Top Layer w10: v1(1486,324) R96.1@1509.62,324
  Bottom Layer w10: Q10.3@1486,300.5 v1(1486,324)
NetR8_2: R8.2 U1.7 | length 90.1
  Bottom Layer w8: R8.2@1283,901.38 1320.62,939 U1.7@1357.51,939
NetR9_1: R9.1 U1.3 | length 136.5
  Bottom Layer w4: U1.3@1546.49,889 1548.99,886.5 R9.1@1682,886.5
NetR12_1: R12.1 S1.8 | length 147.3
  Top Layer w10: v1(580,1923) 692,1923 S1.8@700,1931
  Bottom Layer w10: R12.1@579.96,1899 v1(580,1923)
NetR13_1: R13.1 S1.7 | length 136
  Top Layer w10: v1(580,1873) S1.7@692,1873
  Bottom Layer w10: R13.1@579.96,1849 v1(580,1873)
NetR14_1: R14.1 S1.6 | length 134
  Top Layer w10: v1(581,1823) S1.6@692,1823
  Bottom Layer w10: R14.1@581,1800.04 v1(581,1823)
NetR15_1: R15.1 S1.5 | length 134
  Top Layer w10: v1(581,1773) S1.5@692,1773
  Bottom Layer w10: R15.1@581,1750.04 v1(581,1773)
NetR27_1: R27.1 S3.2 | length 39.1
  Top Layer w12: S3.2@1557.93,1524 R27.1@1597.04,1524
NetR28_2: R28.2 U2.G2 | length 190.5
  Top Layer w4: v1(802,914.37) 803,915.37 837.8,915.37 842.77,920.34 911.91,920.34 U2.G2@921.26,929.69
  Bottom Layer w4: v1(802,914.37) 840,914.37 R28.2@859,895.37
NetR42_1: R42.1 S2.8 | length 87.9
  Top Layer w10: S2.8@1600,1931 1609,1931 v1(1640,1900)
  Bottom Layer w10: R42.1@1604.96,1900 v1(1640,1900)
NetR43_1: R43.1 S2.7 | length 87.9
  Top Layer w10: S2.7@1600,1881 1609,1881 v1(1640,1850)
  Bottom Layer w10: R43.1@1604.96,1850 v1(1640,1850)
NetR44_1: R44.1 S2.6 | length 87.9
  Top Layer w10: S2.6@1600,1831 1609,1831 v1(1640,1800)
  Bottom Layer w10: R44.1@1604.96,1800 v1(1640,1800)
NetR45_1: R45.1 S2.5 | length 87.9
  Top Layer w10: S2.5@1600,1781 1609,1781 v1(1640,1750)
  Bottom Layer w10: R45.1@1604.96,1750 v1(1640,1750)
NetR56_2: R56.2 U2.F1 | length 206.1
  Top Layer w4: v1(802,949.37) 834,949.37 841.19,942.18 889.81,942.18 897,949.37 U2.F1@901.57,949.37
  Bottom Layer w4: v1(802,949.37) 880.89,949.37 885.04,953.52 R56.2@885.04,969.37
NetR81_1: R81.1 R83.2 U5.8 | length 519.6
  Bottom Layer w10: R81.1@325,687.38 325,634.62 R83.2@324,633.62 286,595.62 286,551 333,504 473,504 492,523 492,607.5 506,621.5 U5.8@506,650.88
NetR91_1: R91.1 R93.2 U6.8 | length 467.6
  Bottom Layer w10: R91.1@1219.6,1321.38 1219.6,1276.62 1194,1251.02 1194,1198.96 1225.6,1167.36 1338.36,1167.36 1380,1209 1445,1209 1467.6,1231.6 U6.8@1467.6,1252.88
NetR101_1: R101.1 R103.2 U7.8 | length 529.4
  Bottom Layer w10: U7.8@472,1472.69 445.12,1472.69 423.12,1494.69 340.12,1494.69 318.12,1516.69 318.12,1662.69 350.12,1694.69 434.12,1694.69 439.74,1689.06 R103.2@439.74,1663.69 R101.1@488.5,1663.69
RESETZ: R54.1 U2.F11 | length 723.2
  Top Layer w4: U2.F11@1098.43,949.37 1234.99,949.37 1524.62,1239 1638,1239 R54.1@1683,1194
RPD_G1: R10.1 R22.1 U2.K9 | length 128.6
  Top Layer w4: U2.K9@1059.06,870.63 1049,860.57 1049,841.72 1075.05,815.67 R22.1@1075.05,789 ; R22.1@1078,788.96 R10.1@1110.05,789 R10.1@1110.05,789
RPD_G2: R11.1 R30.1 U2.K10 | length 206.2
  Top Layer w4: U2.K10@1078.74,870.63 1087.7,861.67 1152.33,861.67 1206,808 R11.1@1206,789 ; R11.1@1206.96,789 R11.1@1206,789 ; R30.1@1239,788.96 1206.04,788.96 R11.1@1206,789
SENSEN: R2.1 R3.1 U2.A10 | length 855.1
  Top Layer w4: U2.A10@1078.74,1047.8 1078.74,1064.74 1097,1083 1097,1098 1113,1114 v1(1130,1114)
  MidLayer2 w4: v1(751,584) 980,813 980,990 1104,1114 v1(1130,1114)
  Bottom Layer w4: R2.1@750.04,527.5 R3.1@750.04,562.5 v1@750.04,583.04
SENSEP: R5.1 R6.1 U2.B10 | length 802
  Top Layer w4: U2.B10@1078.74,1028.11 1080.11,1028.11 1088,1036 1088,1061 1115,1088 v1(1115,1095)
  MidLayer2 w4: v1(956,581) 995,581 1173,759 1173,1037 v1(1115,1095)
  Bottom Layer w4: R5.1@929.96,528 R6.1@929.96,563 947.96,581 v1(956,581)
SPI_CLK: R38.2 U1.6 U2.A3 | length 1998.9
  Top Layer w4: R38.2@322.96,900 576,900 762,1086 762,1132 952,1322 v1(992,1322) 992,1308 940.94,1256.94 U2.A3@940.94,1047.8
  MidLayer1 w4: v1(992,1322) 1204,1322 1279,1247 1279,948 1312,915 v1(1423,915)
  Bottom Layer w4: 1376,901 1376,910 1381,915 v1(1423,915)
SPI_CSZ: R4.2 R66.2 U1.1 U2.B3 | length 1741.9
  Top Layer w4: U2.B3@940.94,1028.11 931,1038.06 931,1279 v1(959,1307)
  Top Layer w12: v1@1655.5,699.9 1676.94,699.9 R66.2@1677.04,700
  MidLayer1 w4: v1(959,1307) 959,1317 981,1339 1232,1339 1324,1247 1324,1032 1367,989 v1(1482,989) 1481,990 1639,990 1669,960 1669,718.6 v1(1650.3,699.9)
  Bottom Layer w4: v1(1482,989) U1.1@1546.49,989 1621.62,989 R4.2@1624,991.38
SPI_MISO: R7.2 R62.1 U1.2 U2.A4 | length 1557
  Top Layer w4: U2.A4@960.63,1047.8 960.63,1210.63 v1(994,1244) ; v1(1482,939) 1521,900 R62.1@1677.04,900
  MidLayer1 w4: v1(994,1244) 1024,1274 1151.1,1274 1207,1218.1 1207,896 1252.29,850.71 1456.71,850.71 1482,876 v1(1482,939)
  Bottom Layer w4: v1(1482,939) U1.2@1546.49,939 1550.49,935 1672,935 R7.2@1676.38,939.38
SPI_MOSI: R60.1 U1.5 U2.B4 | length 1487.4
  Top Layer w4: U2.B4@960.63,1028.11 951,1037.74 951,1234 v1(976,1259) ; v1@1423,887 1444,887 1461,904 1461,946 1481,966 1570,966 1604,1000 R60.1@1677.04,1000
  MidLayer1 w4: v1(976,1259) 1018,1301 1178,1301 1242,1237 1242,913 1271,884 v1(1423,884)
  Bottom Layer w4: U1.5@1365.51,847 1415,847 1423,855 v1(1423,884)
SWD_CLK: R24.1 R41.1 U2.G4 | length 978.5
  Top Layer w4: v1(254,566) 306.96,566 R41.1@322.96,550 R24.1@363.04,550 ; v1@945,929 v1(947,929) 959.94,929 U2.G4@960.63,929.69
  MidLayer1 w4: v1(254,566) 254,572 517,835 809.91,835 903.91,929 v1(947,929)
SWD_DATA: R20.1 R39.1 U2.F4 | length 940
  Top Layer w4: v1(253.33,667) 305.96,667 R39.1@322.96,650 R20.1@362.04,650 ; v1(938,948) 959.26,948 U2.F4@960.63,949.37
  MidLayer1 w4: v1(253.33,667) 325,667 503,845 773,845 795,867 823.72,867 904.72,948 v1(938,948)
SYSTEM_3V3: C13.1 C24.1 C25.1 C26.1 C27.1 J5.3 J7.3 L2.2 R27.2 R82.2 U2.B1 U2.H1 | length 4945.8
  Top Layer w6: v1(832,900) 843.63,900 853.63,910 U2.H1@901.57,910 ; v1(859,1037.37) 867.87,1028.5 882.97,1028.5 883.36,1028.11 U2.B1@901.57,1028.11
  Top Layer w16: J7.3@638.5,1666 664,1666 691,1693 v1(691,1710) ; R27.2@1626.96,1524 1653.96,1551 v1(1928,1551) 1979,1500 1979,530 ; J5.3@1699,401 1769,471 1915,471 1974,530
  MidLayer2 w16: v1(691,1710) 1525,1710 1558,1677 1692.05,1677 1818.05,1551 v1(1928,1551) ; v1(750,736) 740,736 725,721 725,512 832,405 1695,405 J5.3@1699,401
  Bottom Layer w6: v1@831,899 v1(832,900) ; v1@861,1033.37 v1@861,1037.37
  Bottom Layer w10: C27.1@697.62,524 C26.1@697.62,606 697.62,665.62 C25.1@698,666 ; L2.2@713.2,996.8 818.43,996.8 v1(859,1037.37) 861,1037.37 881.64,1037.37 C13.1@890.01,1029 ; L2.2@723.1,907.1 762,907.1 772.8,896.3 816.05,896.3 818.75,899 v1@831,899
  Bottom Layer w16: C24.1@709,736 v1(750,736)
SYSTEM_5V: C11.1 C12.1 C35.1 C36.1 C37.1 C38.1 D2.1 D3.1 D4.1 D5.1 D6.1 D7.1 D8.1 D9.1 J5.2 J7.1 L3.2 R92.2 U2.A11 U2.B11 U2.C11 U2.D11 U2.H10 | length 5759.4
  Top Layer w8: v1@1063.8,904.67 1073.41,904.67 U2.H10@1078.74,910
  Top Layer w10: D2.1@450,121.65 450,128 486,164 656,164 715,223 v1(715,364) 490,364 D4.1@455,329 ; D3.1@650,121.65 650,163 ; D5.1@650,321.65 650,361 ; D7.1@1350.5,125.59 1382.91,158 1550,158 ; D8.1@1350.5,325.59 1383.91,359 1606,359 ; D6.1@1550,121.65 1550,158 ; D9.1@1550,321.65 1550,356 ; J5.2@1799,401 1757,359 1606,359 ; 1550,158 1559,158 1606,205 1606,359
  Top Layer w16: 677,1540 677,1499 754,1422 v1(882,1422)
  MidLayer2 w8: v1@1063.8,904.67 1120,960.87 v2(1120,996.37)
  MidLayer2 w10: v1(715,364) 1612,364 1625,351 1720,351 1770,401 J5.2@1799,401
  MidLayer2 w16: v1(882,1422) 904,1444 1177.05,1444 1329.05,1596 1650,1596 v1@1678,1624
  Bottom Layer w16: L3.2@1635.13,1549 1678,1591.87 v1(1678,1626) ; L3.2@1674,1551 L3.2@1676,1553
  Bottom Layer w36: 1150,1060.5 1277.5,1060.5 1291,1074 1613,1074 1661,1122 1661,1255.6 C36.1@1660.6,1256
  Bottom Layer w40: C38.1@1663,1136.4 1736.1,1063.3 1736.1,463.9 J5.2@1799,401
  other v1: 1065,905
  other v2: 1131,1009.37 1120,1022.37 1131,1035.37 1120,1048.37
SYSTEM_RESET: C53.1 R26.2 S3.1 U2.D6 | length 958
  Top Layer w4: v1(961,1011) 977.74,1011 U2.D6@1000,988.74
  Top Layer w10: v1(1286,1481) 1327.96,1522.96 R26.2@1355,1522.96 ; R26.2@1355,1523.96 1382.97,1523.96 1383.01,1524 S3.1@1424.07,1524
  MidLayer1 w4: v1(961,1011) 961,1104 938,1127 938,1356 976,1394 1173,1394 1260,1481 v1(1286,1481)
TIVA_3V3: J2.2 J7.4 | length 529.1
  Top Layer w16: v1(100,1550) 100,1580 118,1598 306,1598 374,1666 J7.4@463.5,1666
  MidLayer2 w16: J2.2@100,1450 v1(100,1550)
TIVA_5V: J2.1 J7.2 | length 370.1
  Top Layer w16: v1(200,1550) 216,1566 J7.2@463.5,1566
  MidLayer2 w16: J2.1@200,1450 v1(200,1550)
UART_RX: R23.2 U2.F2 | length 804.9
  Top Layer w4: R23.2@322.96,1199 R23.2@322.96,1199 v1(323,1221) ; v1(781,949) 795.5,963.5 837.5,963.5 848,953 885,953 890.22,958.22 912,958.22 920.84,949.37 U2.F2@921.26,949.37
  MidLayer1 w4: v1(323,1221) 343,1241 516,1241 672,1085 672,1018 741,949 v1(781,949)
UART_TX: R19.1 U2.E2 | length 829.5
  Top Layer w4: R19.1@322.96,1299 R19.1@322.96,1299 v1(323,1320) ; v1(781,974) 788,981 895,981 897,979 911.31,979 U2.E2@921.26,969.06
  MidLayer1 w4: v1(323,1320) 323,1286 349,1260 523.87,1260 691,1092.87 691,1026 743,974 v1(781,974)
USB2_RP_N: R68.2 U2.K5 | length 1334.1
  Top Layer w4: 971,819 971,861.31 U2.K5@980.32,870.63
  Top Layer w4.8: v1(1650,600) R68.2@1677.04,600
  Top Layer w5.8: v1(750,709) 762.72,696.28 848.78,696.28 970.66,818.16
  MidLayer1 w4.8: v1(750,709) 763.1,695.9 792.96,695.9 925.06,563.8 1508,563.8 1523.2,579 1551,579 1551.06,579.06 1629.06,579.06 v1(1650,600)
USB2_RP_P: R67.2 U2.L5 | length 1327.8
  Top Layer w4: 980.32,819 U2.L5@980.32,850.53
  Top Layer w4.8: v1(1649,550) R67.2@1677.04,550
  Top Layer w5.8: v1(750,673) 762.72,685.72 853.15,685.72 981.21,813.79 981.21,819
  MidLayer1 w4.8: v1(750,673) 763.1,686.1 788.9,686.1 921,554 1512.06,554 1527.26,569.2 1555.06,569.2 1555.12,569.26 1629.74,569.26 v1(1649,550)
VBUS: C7.1 C8.1 C9.1 C10.1 D1.1 J1.A4 J1.A9 J1.B4 J1.B9 L1.2 TP3.1 | length 570.1
  Top Layer w10: J1.B9@947.52,240.35 947.52,271.52 953.42,277.42 J1.A4@953.42,305.31 ; v2(950,331) 950,308.74 J1.A4@953.42,305.31 ; v2@950,337.67 953.42,334.24 J1.A4@953.42,305.31 ; J1.B4@1045.94,240.35 1045.94,270.94 1051.85,276.85 J1.A9@1051.85,305.31
  Top Layer w16: v2(942,345.67) 950,337.67 v2(950,331) ; J1.A9@1052,319 v2(1054,331) 1054,335 v2(1064,345)
  Top Layer w40: 1459,625 TP3.1@1459,793.71
  Bottom Layer w6: 1303,641 1304,640
  Bottom Layer w40: 1305,630 v1@1461,630
  other v1: 1451,620 1469,630 1451,641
